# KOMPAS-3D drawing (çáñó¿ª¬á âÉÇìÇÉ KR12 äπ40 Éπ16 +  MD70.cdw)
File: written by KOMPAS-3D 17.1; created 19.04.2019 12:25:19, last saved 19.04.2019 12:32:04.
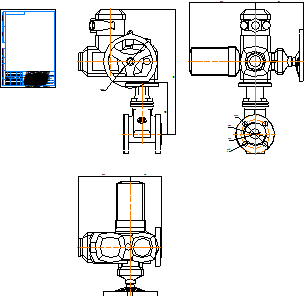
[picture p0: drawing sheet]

Sheet 1: A4, portrait

Title block, sheet 1: name: Задвижка ГРАНАР KR12 Ду40 Ру16 + / MD70; material: Внимание! Данный продукт является объектом авторского права ООО «Торговый Дом АДЛ». / Запрещается изменение, копирование, распространение / (в том числе путем копирования на другие сайты и ресурсы в Интернете) / или любое иное использование информации и объектов без предварительного / согласия правообладателя (ООО «Торговый Дом АДЛ»).; mass: 76,88; sheets: 1; organisation: ООО "Торговый дом АДЛ"; sheet format: A4; stored path: \\adlc.lan\data\АДЛ_ПКД\3D-модели\ADL production\Клиновые задвижки серии KR ГРАНАР\Клиновые задвижки KR12 с эл.приводами Смартгир\KOMPAS 2D\Задвижка ГРАНАР KR12 Ду40 Ру16 +  MD70.cdw

Views: Вид 1, Проекционный вид 2, Проекционный вид 3
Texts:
  user
Dimensions and other numbers on the sheet: 196; 478; 110; 205; 253; 187; 150; 40; 19; 4 Отв.; 200; 118; 1:1; 1; 76,88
